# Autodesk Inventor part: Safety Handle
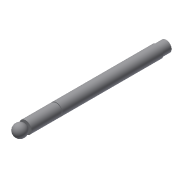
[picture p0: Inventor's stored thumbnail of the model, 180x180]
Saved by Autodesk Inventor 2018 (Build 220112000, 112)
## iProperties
Shininess: 77.0
Length Units: 11269
Angle Units: 11279
Time Units: 11290
Mass Units: 11283
Length Display Precision: 3
Angle Display Precision: 2
Created: 2002-02
Part Number: Safety Handle
Document SubType Name: Modeling
Designer: ***
Density: 1 g/cm^3
Material: Generic
Mass: 54.3914 g
Surface Area: 130.219 cm^2
Volume: 54.3914 cm^3
Appearance: Default
Density: 0.0
Volumn: 0.0
Area: 0.0
PropertySet Name: Model Information
Control State: 0
Master: False
Checked Out: False
Author: ***
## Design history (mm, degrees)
sketch "Sketch1"
  geometry: L1 (0, 205)-(8, 205); L2 (8, 205)-(8, 192); L3 (8, 192)-(9, 192); L4 (9, 192)-(9, 45); L5 (9, 45)-(8, 45); L6 (8, 45)-(8, 43); L7 (8, 43)-(9, 43); L8 (9, 43)-(9, 0); L9 (9, 0)-(0, 0); L10 (0, 0)-(0, 205)
  constraints: 20 end point, 7 parallel, 1 collinear, 1 horizontal, 1 perpendicular
  dimensions: "d0" = 13 distance of L1.end L2.end; "d1" = 2 distance of L4.end L7.end; "d2" = 43 distance of L7.end L8.end; "d3" = 205 distance of L9.end L1.start; "d4" = 16 diameter of L2 L10; "d5" = 18 diameter of L4 L10; "d6" = 16 diameter of L6.end L10
revolve "Revolution1" sketch "Sketch1" stored, may be unused: angle "d7" = 90 deg
sketch "Sketch2"
  geometry: L1 (0, 1)-(0, -17); L2 (-9, 0)-(9, 0) reference; A1 r 9 centre (0, -8) between (0, -17) and (0, 1)
  constraints: 2 end point, 2 point on circle, 1 centre point, 1 midpoint, 1 vertical
  dimensions: "d8" = 9 radius of A1; "d9" = 1 distance from line of L2 L1.start
revolve "Revolution2" sketch "Sketch2" stored, may be unused: angle "d10" = 90 deg
body "Solid1"
